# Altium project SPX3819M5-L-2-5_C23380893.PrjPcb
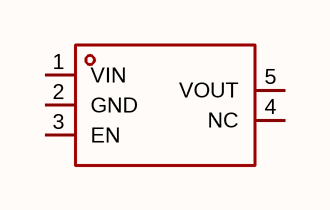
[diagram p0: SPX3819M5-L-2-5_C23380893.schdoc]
1 sheet, 1 parts. Net scope: global (net labels, ports and power ports of the same name join across sheets).

## Sheet SPX3819M5-L-2-5_C23380893.schdoc
size 127 x 101 mm

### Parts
U?  spx3819m5-l-2-5_c23380893  [SOT-23-5_L2.9-W1.6-P0.95-LS2.8-BR]  (value not drawn)

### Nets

Not connected (* = marked no-connect by the designer): U? 1(VIN) 2(GND) 3(EN) 4(NC) 5(VOUT)

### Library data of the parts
U? = spx3819m5-l-2-5_c23380893: 输出极性:正极;工作电压:20V;输出电压:2.5V;输出电流:500mA;电源纹波抑制比(PSRR):70dB@(1kHz);输出类型:固定;; Manufacturer: TECH PUBLIC(台舟); AddInBom: yes; ModelId: 7ba65df16e7b4570af156e925f9c37fe; ModelTransform: 114.173,114.173,0,90,0,0,0,0,0; Output Configuration: 正极; Voltage - Supply: 20V; Output Voltage: 2.5V; Output Current: 500mA; Voltage Dropout: 350mV@(100mA); standby current: 5uA; Output Type: 固定; Number of Outputs: 1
